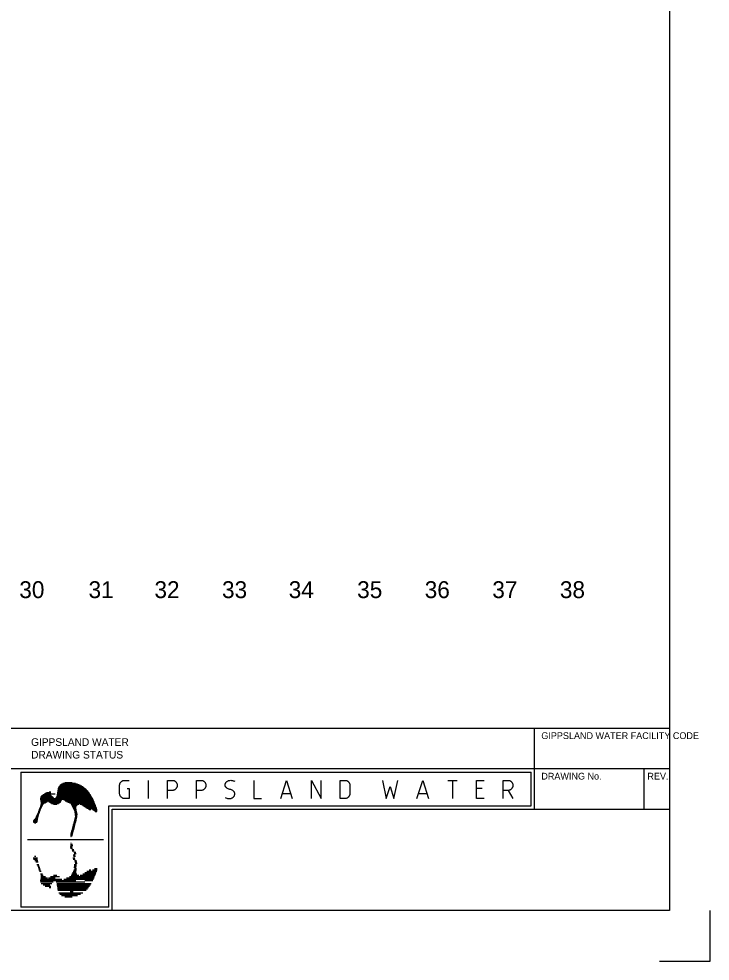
# Model space of a CAD drawing. Extents: x 0 to 841, y 0 to 594.
# Drawn here: x 636.4 to 841, y 0 to 279 of the extents above; entities that cross this region are included whole.
import ezdxf

# ---------------------------------------------------------------- set-up
doc = ezdxf.new("R2010")
doc.units = 0
doc.layers.add('A1BORDER', color=7, linetype='Continuous')
doc.layers.add('Level 1', color=7, linetype='Continuous')

msp = doc.modelspace()

# ---------------------------------------------------------------- linework, layer by layer
at = {"layer": 'A1BORDER'}
for p, q in [((829, 581), (829, 15)), ((592.5, 69), (829, 69)), ((789, 45), (789, 69)), ((28, 57), (829, 57)), ((637, 56), (788, 56)), ((637, 56), (637, 16)), ((788, 46), (788, 56)), ((821.5, 45), (821.5, 57)), ((647.81, 50.32), (656.86, 50.32)), ((647.85, 50.52), (656.69, 50.52)), ((647.88, 50.72), (656.5, 50.72)), ((647.91, 50.92), (656.3, 50.92)), ((647.96, 51.12), (656.08, 51.12)), ((648.03, 51.32), (655.85, 51.32)), ((648.12, 51.52), (655.59, 51.52)), ((648.23, 51.72), (655.31, 51.72)), ((648.37, 51.92), (655, 51.92)), ((648.53, 52.12), (654.64, 52.12)), ((648.74, 52.32), (654.24, 52.32)), ((649.02, 52.52), (653.76, 52.52)), ((649.39, 52.72), (653.15, 52.72)), ((650.01, 52.92), (652.2, 52.92)), ((642.73, 48.12), (658.25, 48.12)), ((642.74, 47.92), (658.35, 47.92)), ((642.75, 48.32), (646.79, 48.32)), ((642.79, 47.72), (649.08, 47.72)), ((642.81, 48.52), (646.55, 48.52)), ((642.83, 47.52), (648.95, 47.52)), ((642.9, 48.72), (646.37, 48.72)), ((643.04, 48.92), (646.16, 48.92)), ((643.26, 49.12), (645.9, 49.12)), ((643.54, 49.32), (645.57, 49.32)), ((643.85, 49.52), (647.09, 49.52)), ((644.18, 49.72), (645.89, 49.72)), ((644.54, 49.92), (645.36, 49.92)), ((645.37, 50.12), (645.86, 50.12)), ((647.19, 48.32), (658.14, 48.32)), ((647.42, 48.52), (658.03, 48.52)), ((647.54, 48.72), (657.92, 48.72)), ((647.61, 48.92), (657.8, 48.92)), ((647.63, 49.12), (657.68, 49.12)), ((647.66, 49.32), (657.57, 49.32)), ((647.69, 49.52), (657.44, 49.52)), ((647.71, 49.72), (657.31, 49.72)), ((647.75, 49.92), (657.17, 49.92)), ((647.78, 50.12), (657.02, 50.12)), ((649.72, 47.72), (658.45, 47.72)), ((650.12, 47.52), (658.55, 47.52)), ((642.28, 44.72), (642.76, 44.72)), ((642.35, 44.92), (642.83, 44.92)), ((642.43, 45.12), (642.9, 45.12)), ((642.5, 45.32), (643, 45.32)), ((642.57, 45.52), (643.1, 45.52)), ((642.65, 45.72), (643.2, 45.72)), ((642.72, 45.92), (643.3, 45.92)), ((642.79, 46.12), (643.4, 46.12)), ((642.84, 46.32), (643.5, 46.32)), ((642.85, 47.31), (644.88, 47.31)), ((642.87, 47.12), (644.57, 47.12)), ((642.87, 46.52), (643.6, 46.52)), ((642.88, 46.92), (644.23, 46.92)), ((642.88, 46.72), (643.83, 46.72)), ((645.14, 47.31), (648.83, 47.31)), ((645.49, 47.12), (648.67, 47.12)), ((645.76, 46.92), (648.42, 46.92)), ((646.05, 46.72), (648.11, 46.72)), ((646.62, 46.52), (647.67, 46.52)), ((650.48, 47.31), (658.64, 47.31)), ((650.87, 47.12), (658.73, 47.12)), ((651.36, 46.92), (658.82, 46.92)), ((651.76, 46.72), (658.9, 46.72)), ((651.88, 46.52), (654.15, 46.52)), ((651.99, 46.32), (653.71, 46.32)), ((652.1, 46.12), (653.52, 46.12)), ((652.2, 45.92), (653.4, 45.92)), ((652.31, 45.72), (653.33, 45.72)), ((652.41, 45.52), (653.31, 45.52)), ((652.5, 45.32), (653.34, 45.32)), ((652.6, 45.12), (653.38, 45.12)), ((652.69, 44.92), (653.41, 44.92)), ((652.78, 44.72), (653.44, 44.72)), ((654.57, 46.52), (658.99, 46.52)), ((655, 46.32), (659.07, 46.32)), ((655.31, 46.12), (659.14, 46.12)), ((655.62, 45.92), (659.22, 45.92)), ((655.93, 45.72), (659.29, 45.72)), ((656.24, 45.52), (659.35, 45.52)), ((656.55, 45.32), (659.42, 45.32)), ((656.86, 45.12), (657.74, 45.12)), ((657.17, 44.92), (657.68, 44.92)), ((657.51, 44.72), (657.54, 44.72)), ((657.91, 45.12), (659.48, 45.12)), ((658.19, 44.92), (659.54, 44.92)), ((658.47, 44.72), (659.59, 44.72)), ((663, 46), (788, 46)), ((663, 16), (663, 46)), ((664, 45), (829, 45)), ((664, 15), (664, 45)), ((640.9, 41.92), (641.97, 41.92)), ((641.1, 42.12), (642, 42.12)), ((641.25, 42.31), (642.04, 42.31)), ((641.37, 42.52), (642.09, 42.52)), ((641.46, 42.72), (642.15, 42.72)), ((641.55, 42.92), (642.2, 42.92)), ((641.64, 43.12), (642.25, 43.12)), ((641.73, 43.32), (642.3, 43.32)), ((641.82, 43.51), (642.35, 43.51)), ((641.91, 43.72), (642.41, 43.72)), ((641.99, 43.92), (642.48, 43.92)), ((642.06, 44.12), (642.55, 44.12)), ((642.13, 44.32), (642.62, 44.32)), ((642.21, 44.52), (642.69, 44.52)), ((652.83, 44.52), (653.48, 44.52)), ((652.85, 41.92), (653.45, 41.92)), ((652.86, 44.32), (653.53, 44.32)), ((652.89, 44.12), (653.57, 44.12)), ((652.9, 42.12), (653.49, 42.12)), ((652.91, 43.92), (653.62, 43.92)), ((652.94, 43.72), (653.67, 43.72)), ((652.95, 42.31), (653.53, 42.31)), ((652.97, 43.51), (653.71, 43.51)), ((652.99, 42.52), (653.57, 42.52)), ((653, 43.32), (653.69, 43.32)), ((653.02, 43.12), (653.67, 43.12)), ((653.03, 42.72), (653.61, 42.72)), ((653.05, 42.92), (653.64, 42.92)), ((658.75, 44.52), (659.58, 44.52)), ((659.02, 44.32), (659.47, 44.32)), ((640.62, 41.32), (641.88, 41.32)), ((640.63, 41.52), (641.93, 41.52)), ((640.72, 41.12), (641.73, 41.12)), ((640.73, 41.72), (641.95, 41.72)), ((641.03, 40.92), (641.43, 40.92)), ((652.09, 39.12), (652.72, 39.12)), ((652.14, 39.32), (652.77, 39.32)), ((652.2, 39.52), (652.82, 39.52)), ((652.25, 39.72), (652.88, 39.72)), ((652.3, 39.92), (652.93, 39.92)), ((652.36, 40.12), (652.99, 40.12)), ((652.41, 40.32), (653.04, 40.32)), ((652.47, 40.52), (653.1, 40.52)), ((652.52, 40.72), (653.15, 40.72)), ((652.57, 40.92), (653.2, 40.92)), ((652.63, 41.12), (653.26, 41.12)), ((652.68, 41.32), (653.31, 41.32)), ((652.74, 41.52), (653.37, 41.52)), ((652.79, 41.72), (653.41, 41.72)), ((651.63, 37.32), (652.23, 37.32)), ((651.64, 37.12), (652.17, 37.12)), ((651.65, 37.52), (652.28, 37.52)), ((651.71, 37.72), (652.34, 37.72)), ((651.76, 37.92), (652.39, 37.92)), ((651.79, 36.92), (651.9, 36.92)), ((651.82, 38.12), (652.44, 38.12)), ((651.87, 38.32), (652.5, 38.32)), ((651.92, 38.52), (652.55, 38.52)), ((651.98, 38.72), (652.61, 38.72)), ((652.03, 38.92), (652.66, 38.92)), ((638.93, 35.98), (661.47, 35.98)), ((651.54, 33.84), (652.17, 33.84)), ((651.63, 34.64), (652.23, 34.64)), ((651.71, 34.24), (652.34, 34.24)), ((651.79, 35.04), (651.9, 35.04)), ((641.03, 31.04), (641.43, 31.04)), ((651.65, 33.44), (652.28, 33.44)), ((652.03, 33.04), (652.66, 33.04)), ((652.14, 32.64), (652.77, 32.64)), ((652.47, 31.44), (653.1, 31.44)), ((652.57, 31.04), (653.2, 31.04)), ((652.66, 32.24), (653.29, 32.24)), ((652.77, 31.84), (653.4, 31.84)), ((640.62, 30.64), (641.88, 30.64)), ((640.73, 30.24), (641.95, 30.24)), ((641.1, 29.84), (642, 29.84)), ((641.37, 29.44), (642.09, 29.44)), ((641.73, 28.64), (642.3, 28.64)), ((641.91, 28.24), (642.41, 28.24)), ((652.34, 30.64), (652.97, 30.64)), ((652.45, 30.24), (653.07, 30.24)), ((652.72, 28.24), (653.44, 28.24)), ((652.77, 28.64), (653.46, 28.64)), ((652.9, 29.84), (653.49, 29.84)), ((652.99, 29.44), (653.57, 29.44)), ((653.05, 29.04), (653.64, 29.04)), ((642.06, 27.84), (642.55, 27.84)), ((642.21, 27.44), (642.69, 27.44)), ((642.35, 27.04), (642.83, 27.04)), ((642.5, 26.64), (643, 26.64)), ((642.79, 25.84), (643.4, 25.84)), ((642.87, 25.44), (643.6, 25.44)), ((646.62, 25.44), (647.67, 25.44)), ((651.88, 25.44), (654.15, 25.44)), ((652.1, 25.84), (653.52, 25.84)), ((652.31, 26.24), (653.33, 26.24)), ((652.5, 26.64), (653.34, 26.64)), ((652.66, 27.84), (653.35, 27.84)), ((652.69, 27.04), (653.41, 27.04)), ((652.83, 27.44), (653.48, 27.44)), ((654.57, 25.44), (658.99, 25.44)), ((655.31, 25.84), (659.14, 25.84)), ((655.93, 26.24), (659.29, 26.24)), ((656.55, 26.64), (659.42, 26.64)), ((657.17, 27.04), (657.68, 27.04)), ((658.19, 27.04), (659.54, 27.04)), ((658.75, 27.44), (659.58, 27.44)), ((642.73, 23.84), (653.27, 23.84)), ((642.79, 24.24), (649.08, 24.24)), ((642.81, 23.44), (646.55, 23.44)), ((642.85, 24.65), (644.88, 24.65)), ((642.88, 25.04), (644.23, 25.04)), ((643.04, 23.04), (646.16, 23.04)), ((643.54, 22.64), (645.57, 22.64)), ((645.14, 24.65), (647.18, 24.65)), ((645.76, 25.04), (648.42, 25.04)), ((647.42, 23.44), (655.89, 23.44)), ((647.61, 23.04), (657.8, 23.04)), ((647.66, 22.64), (657.57, 22.64)), ((649.72, 24.24), (658.45, 24.24)), ((650.48, 24.65), (658.64, 24.65)), ((651.36, 25.04), (658.82, 25.04)), ((655.94, 23.84), (658.25, 23.84)), ((644.18, 22.24), (645.89, 22.24)), ((645.37, 21.84), (645.86, 21.84)), ((647.71, 22.24), (657.31, 22.24)), ((647.78, 21.84), (657.02, 21.84)), ((647.85, 21.44), (656.69, 21.44)), ((647.91, 21.04), (656.3, 21.04)), ((648.23, 20.24), (655.31, 20.24)), ((648.53, 19.84), (654.64, 19.84)), ((651.57, 20.64), (652.44, 20.64)), ((649.02, 19.44), (653.76, 19.44)), ((650.01, 19.04), (652.2, 19.04)), ((829, 15), (28, 15)), ((663, 16), (637, 16)), ((829, 15), (829, 15)), ((841, 0), (841, 15)), ((826, 0), (841, 0))]:
    msp.add_line(p, q, dxfattribs=at)
for points in [[(668.49, 51.15), (669.06, 51.15), (669.06, 48.16), (667.64, 48.16), (667.51, 48.16), (667.39, 48.18), (667.28, 48.21), (667.15, 48.25), (667.04, 48.3), (666.93, 48.36), (666.82, 48.43), (666.73, 48.51), (666.64, 48.6), (666.55, 48.7), (666.48, 48.8), (666.41, 48.91), (666.35, 49.02), (666.31, 49.14), (666.27, 49.27), (666.24, 49.39), (666.22, 49.52), (666.22, 49.66), (666.22, 52.05), (666.22, 52.18), (666.24, 52.31), (666.27, 52.43), (666.31, 52.56), (666.35, 52.67), (666.41, 52.79), (666.48, 52.9), (666.55, 53), (666.64, 53.1), (666.73, 53.19), (666.82, 53.27), (666.93, 53.34), (667.04, 53.4), (667.15, 53.45), (667.28, 53.49), (667.39, 53.52), (667.51, 53.54), (667.64, 53.54), (669.06, 53.54)], [(674.74, 48.16), (674.74, 53.54)], [(680.42, 48.16), (680.42, 53.54), (681.84, 53.54), (681.96, 53.54), (682.08, 53.52), (682.2, 53.49), (682.32, 53.45), (682.43, 53.4), (682.54, 53.34), (682.65, 53.27), (682.74, 53.19), (682.84, 53.1), (682.92, 53), (682.99, 52.9), (683.06, 52.79), (683.12, 52.67), (683.17, 52.56), (683.21, 52.43), (683.23, 52.31), (683.25, 52.18), (683.26, 52.05), (683.25, 51.91), (683.23, 51.78), (683.21, 51.66), (683.17, 51.53), (683.12, 51.42), (683.06, 51.3), (682.99, 51.19), (682.92, 51.09), (682.84, 50.99), (682.74, 50.9), (682.65, 50.82), (682.54, 50.75), (682.43, 50.69), (682.32, 50.64), (682.2, 50.6), (682.08, 50.57), (681.96, 50.55), (681.84, 50.55), (680.42, 50.55)], [(688.93, 48.16), (688.93, 53.54), (690.35, 53.54), (690.47, 53.54), (690.59, 53.52), (690.71, 53.49), (690.83, 53.45), (690.94, 53.4), (691.05, 53.34), (691.16, 53.27), (691.26, 53.19), (691.35, 53.1), (691.43, 53), (691.51, 52.9), (691.57, 52.79), (691.63, 52.67), (691.68, 52.56), (691.72, 52.43), (691.75, 52.31), (691.76, 52.18), (691.77, 52.05), (691.76, 51.91), (691.75, 51.78), (691.72, 51.66), (691.68, 51.53), (691.63, 51.42), (691.57, 51.3), (691.51, 51.19), (691.43, 51.09), (691.35, 50.99), (691.26, 50.9), (691.16, 50.82), (691.05, 50.75), (690.94, 50.69), (690.83, 50.64), (690.71, 50.6), (690.59, 50.57), (690.47, 50.55), (690.35, 50.55), (688.93, 50.55)], [(697.45, 48.46), (697.67, 48.36), (697.9, 48.27), (698.12, 48.21), (698.36, 48.17), (698.6, 48.16), (698.84, 48.16), (698.87, 48.16), (699.03, 48.18), (699.18, 48.21), (699.33, 48.26), (699.48, 48.32), (699.62, 48.4), (699.72, 48.46), (699.81, 48.53), (699.9, 48.61), (699.98, 48.69), (700.05, 48.78), (700.11, 48.88), (700.17, 48.99), (700.22, 49.09), (700.25, 49.21), (700.28, 49.32), (700.29, 49.36), (700.3, 49.44), (700.3, 49.52), (700.3, 49.61), (700.29, 49.69), (700.27, 49.77), (700.25, 49.86), (700.22, 49.93), (700.18, 50.01), (700.14, 50.09), (700.09, 50.15), (700.04, 50.21), (700.01, 50.25), (699.85, 50.39), (699.69, 50.51), (699.52, 50.61), (699.34, 50.7), (699.15, 50.78), (698.95, 50.83), (698.87, 50.85), (698.68, 50.9), (698.49, 50.96), (698.3, 51.04), (698.12, 51.14), (697.96, 51.26), (697.8, 51.39), (697.73, 51.45), (697.67, 51.51), (697.62, 51.57), (697.58, 51.64), (697.53, 51.71), (697.5, 51.79), (697.47, 51.87), (697.46, 51.95), (697.44, 52.04), (697.43, 52.12), (697.43, 52.21), (697.44, 52.29), (697.45, 52.35), (697.47, 52.46), (697.51, 52.58), (697.55, 52.69), (697.61, 52.79), (697.67, 52.89), (697.74, 52.99), (697.82, 53.07), (697.9, 53.15), (697.99, 53.23), (698.02, 53.24), (698.15, 53.33), (698.3, 53.4), (698.44, 53.45), (698.6, 53.5), (698.75, 53.52), (698.87, 53.54), (699.11, 53.55), (699.35, 53.53), (699.58, 53.49), (699.82, 53.43), (700.04, 53.35), (700.27, 53.25)], [(705.96, 53.54), (705.96, 48.16), (708.23, 48.16)], [(713.91, 48.16), (715.61, 53.54), (717.32, 48.16)], [(722.99, 48.16), (722.99, 53.54), (725.83, 48.16), (725.83, 53.54)], [(731.52, 48.16), (731.52, 53.54), (732.94, 53.54), (733.06, 53.54), (733.18, 53.52), (733.3, 53.49), (733.42, 53.45), (733.53, 53.4), (733.64, 53.34), (733.75, 53.27), (733.84, 53.19), (733.94, 53.1), (734.02, 53), (734.09, 52.9), (734.16, 52.79), (734.22, 52.67), (734.27, 52.56), (734.31, 52.43), (734.33, 52.31), (734.35, 52.18), (734.36, 52.05), (734.36, 49.66), (734.35, 49.52), (734.33, 49.39), (734.31, 49.27), (734.27, 49.14), (734.22, 49.02), (734.16, 48.91), (734.09, 48.8), (734.02, 48.7), (733.94, 48.6), (733.84, 48.51), (733.75, 48.43), (733.64, 48.36), (733.53, 48.3), (733.42, 48.25), (733.3, 48.21), (733.18, 48.18), (733.06, 48.16), (732.94, 48.16), (731.52, 48.16)], [(744.01, 53.54), (745.14, 48.16), (746.28, 51.75), (747.41, 48.16), (748.55, 53.54)], [(754.22, 48.16), (755.92, 53.54), (757.63, 48.16)], [(763.31, 53.54), (766.15, 53.54)], [(764.73, 53.54), (764.73, 48.16)], [(774.09, 48.16), (771.82, 48.16), (771.82, 53.54), (774.09, 53.54)], [(779.78, 48.16), (779.78, 53.54), (781.2, 53.54), (781.32, 53.54), (781.44, 53.52), (781.56, 53.49), (781.68, 53.45), (781.79, 53.4), (781.9, 53.34), (782.01, 53.27), (782.1, 53.19), (782.2, 53.1), (782.28, 53), (782.35, 52.9), (782.42, 52.79), (782.48, 52.67), (782.53, 52.56), (782.56, 52.43), (782.59, 52.31), (782.61, 52.18), (782.61, 52.05), (782.61, 51.91), (782.59, 51.78), (782.56, 51.66), (782.53, 51.53), (782.48, 51.42), (782.42, 51.3), (782.35, 51.19), (782.28, 51.09), (782.2, 50.99), (782.1, 50.9), (782.01, 50.82), (781.9, 50.75), (781.79, 50.69), (781.68, 50.64), (781.56, 50.6), (781.44, 50.57), (781.32, 50.55), (781.2, 50.55), (779.78, 50.55)], [(773.53, 51.15), (771.82, 51.15)], [(781.2, 50.55), (782.61, 48.16)], [(714.48, 49.66), (716.75, 49.66)], [(754.79, 49.66), (757.06, 49.66)]]:
    msp.add_lwpolyline(points, dxfattribs=at)

# ---------------------------------------------------------------- texts
for s, height, p in [('GIPPSLAND WATER FACILITY CODE', 2, (791.03, 65.77)), ('GIPPSLAND WATER', 2.25, (640, 63.75)), ('DRAWING STATUS', 2.25, (640, 60)), ('DRAWING No.', 2, (791.03, 53.77)), ('REV.', 2, (822.43, 53.77))]:
    msp.add_text(s, height=height, dxfattribs=at).set_placement(p)
at = {"layer": 'Level 1'}
for s, p in [('30', (636.52, 107.5)), ('31', (657.01, 107.5)), ('32', (676.52, 107.5)), ('33', (696.52, 107.5)), ('34', (716.26, 107.5)), ('35', (736.52, 107.5)), ('36', (756.52, 107.5)), ('37', (776.52, 107.5)), ('38', (796.52, 107.5))]:
    msp.add_text(s, height=5, dxfattribs=at).set_placement(p)

doc.saveas('drawing.dxf')
